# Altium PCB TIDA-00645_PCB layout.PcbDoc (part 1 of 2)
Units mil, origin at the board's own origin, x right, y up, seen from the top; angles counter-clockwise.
Board outline 3000 x 2000 mil, 2 copper layers (Top Layer, Bottom Layer), stack 62 mil thick; 97 components, 65 nets, 273 pads, 637 vias.
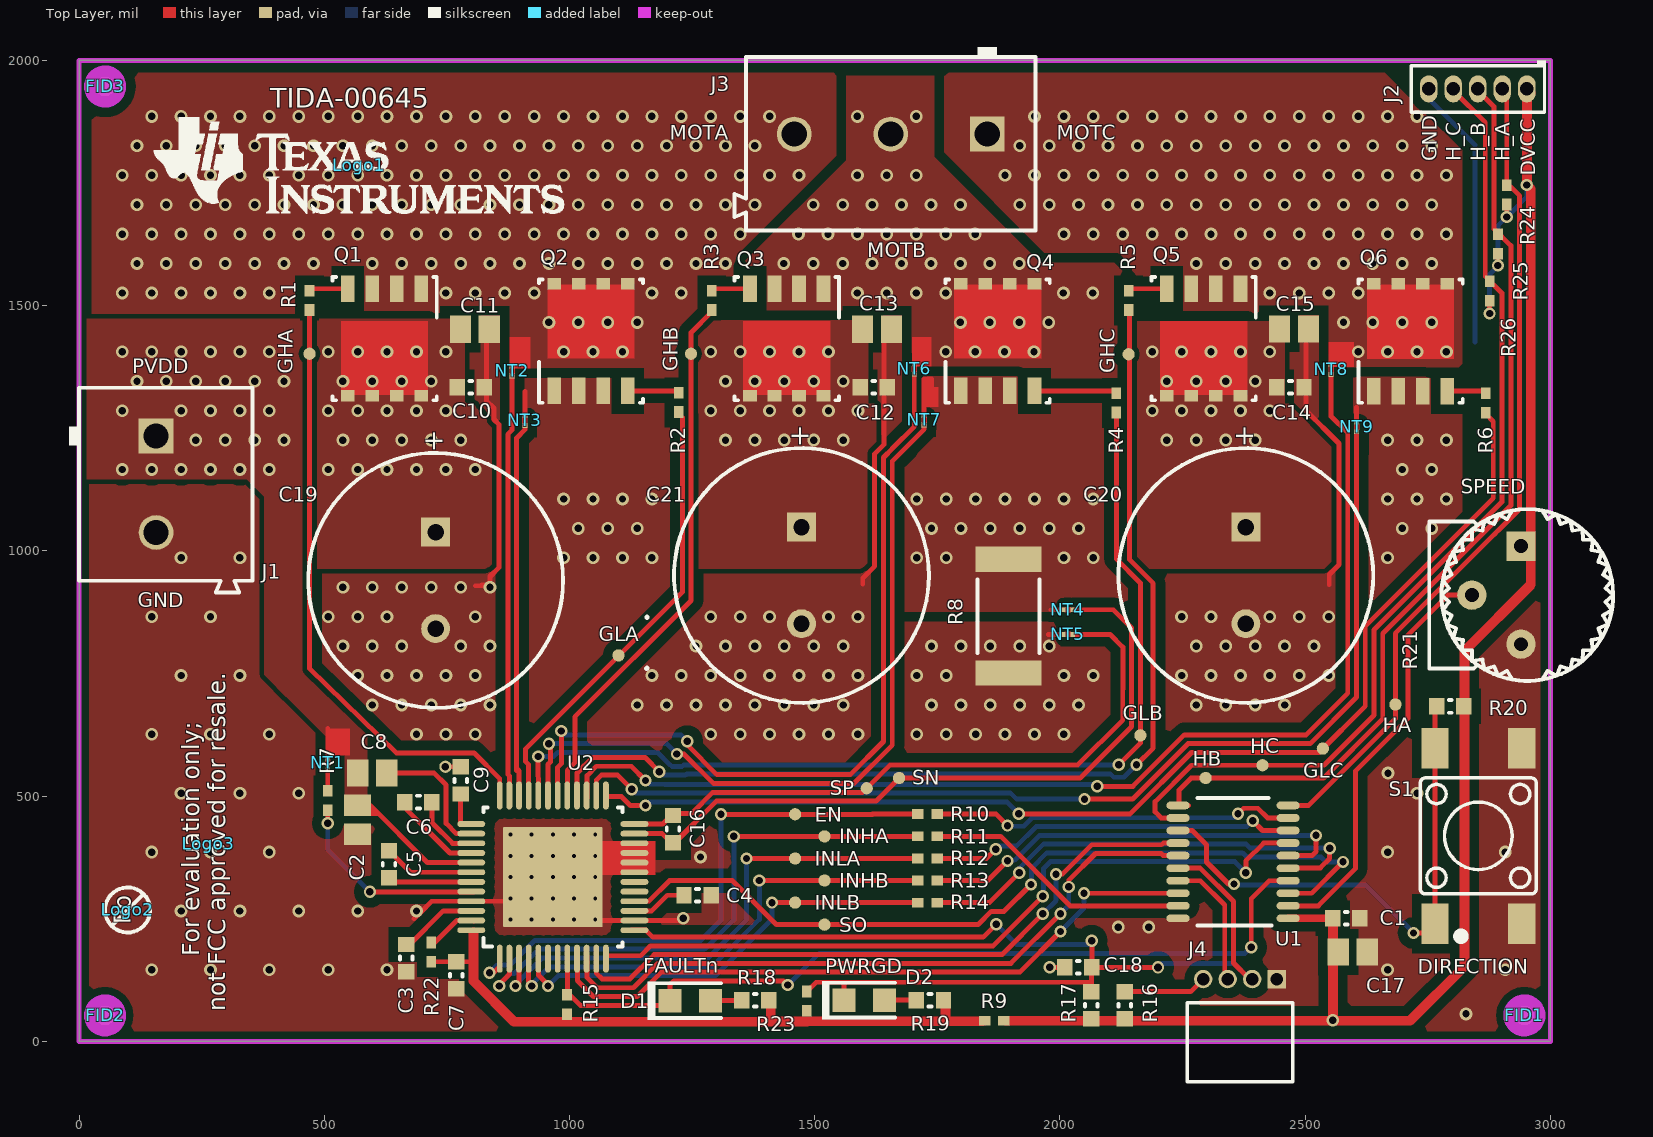
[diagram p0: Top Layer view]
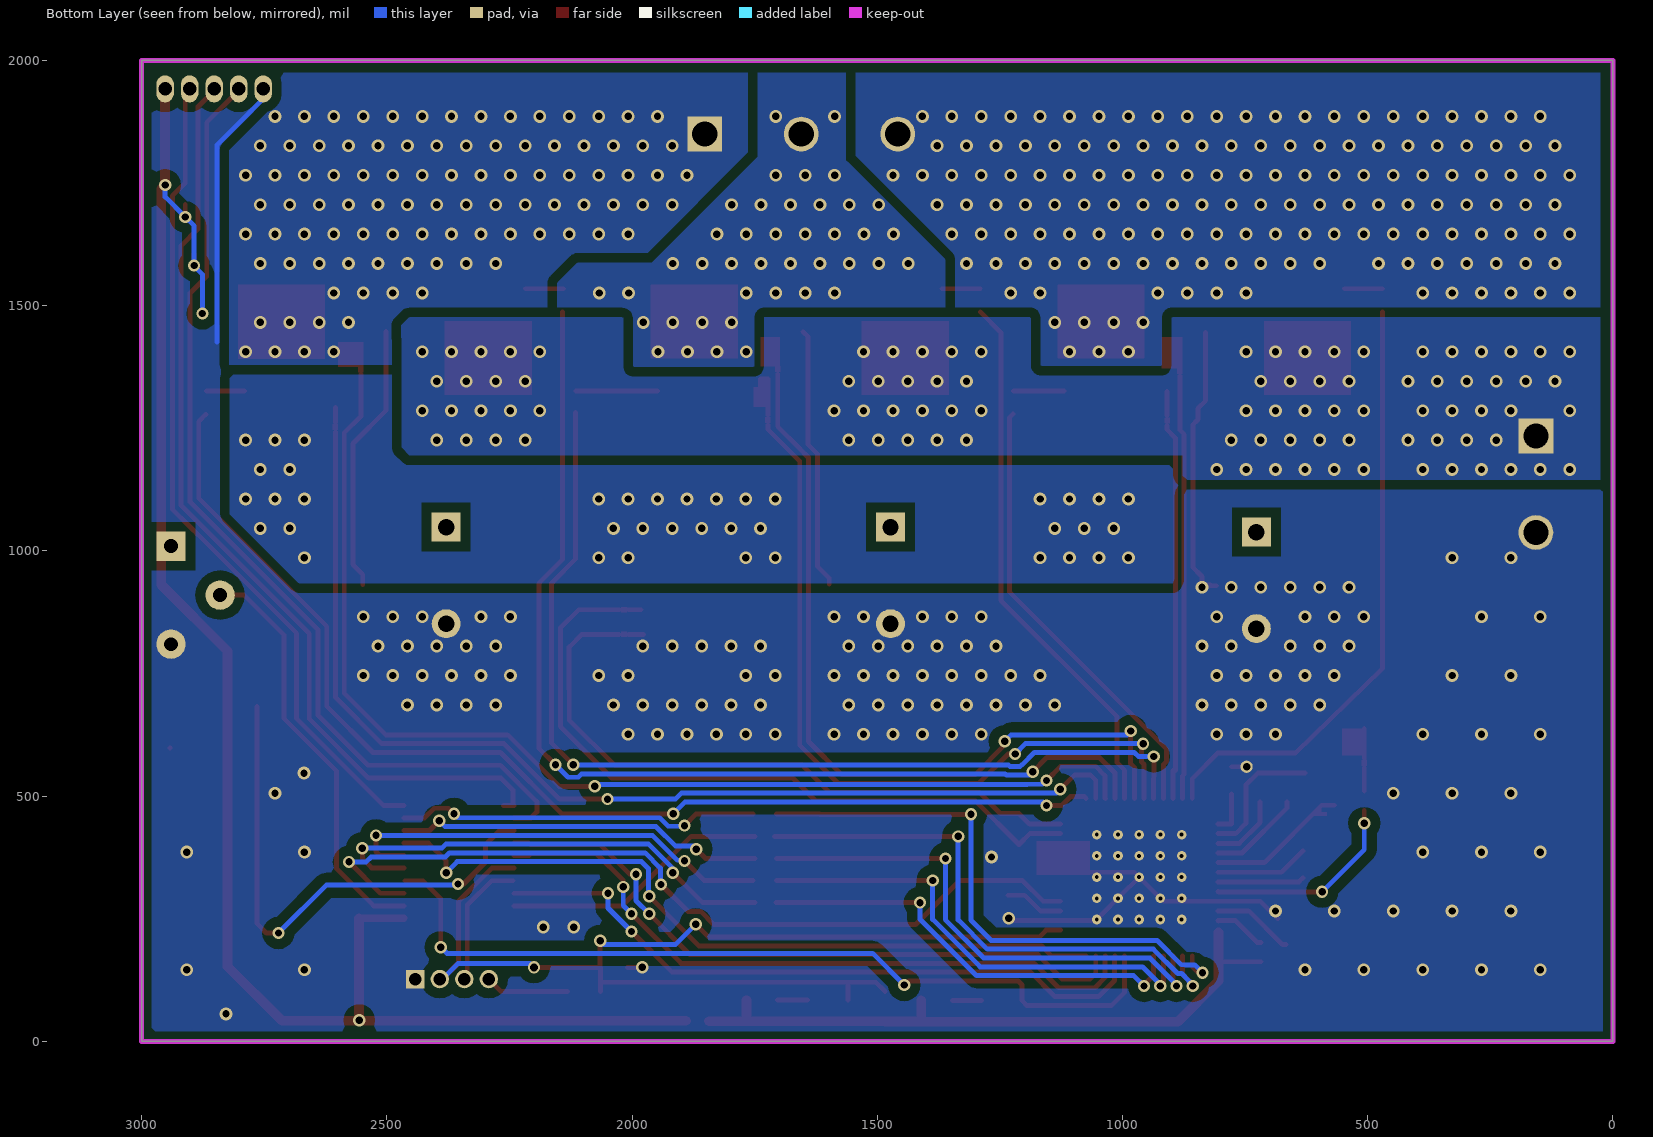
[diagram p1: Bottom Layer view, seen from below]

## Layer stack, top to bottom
Top Solder: solder mask 0.4, Solder Resist, Dk 3.5
Top Layer: signal copper 1.4
Dielectric1: core 59.2, FR-4, Dk 4.8
Bottom Layer: signal copper 1.4
Bottom Solder: solder mask 0.4, Solder Resist, Dk 3.5

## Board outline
0,0 0,2000 3000,2000 3000,0 0,0

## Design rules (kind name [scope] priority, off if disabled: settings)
AcuteAngle [All] p1: minimum=4.50000000000000E+0001 checktracksonly=FALSE
AssemblyTestPointUsage [All] p1: valid=2
Clearance Clearance_1 [InNamedPolygon('Top Layer-PVDD')] p1: gap=10
Clearance Clearance_Keepouts [((IsTrack Or IsArc) And Not InPoly) And IsFree and IsKeepOut vs ((IsTrack Or IsArc) And Not InPoly) And IsFree and IsKeepOut] p2: gap=0
Clearance Clearance_BoardEdge_MountingHoles [OnCopper and InComponentClass('Mounting Holes') vs IsKeepOut] p3: gap=40
Clearance Clearance_BoardEdge_Poly [OnCopper and InPoly vs IsKeepOut] p4: gap=15
Clearance Clearance_BoardEdge [OnCopper and Not InComponentClass('Logo') and not InComponentClass('FiducialMark') and not InRegion(1000,500,4000,800) and Not IsKeepout vs IsKeepOut] p5: gap=25
Clearance Clearance_Poly [InPolygon] p6: gap=20
Clearance [All] p7: gap=7.87
ComponentClearance ComponentClearance_MountingHoles_FiducialMarks [InComponentClass('Mounting Holes') vs InComponentClass('FiducialMark')] p1: gap=50 collisioncheckmode=3 verticalgap=10 showdistances=FALSE
ComponentClearance ComponentClearance_Shunt [InComponentClass('Header') vs InComponentClass('Shunt')] p2: gap=0 collisioncheckmode=3 verticalgap=0 showdistances=FALSE
ComponentClearance ComponentClearance_Logo [InComponentClass('Logo')] p3: gap=50 collisioncheckmode=3 verticalgap=10 showdistances=FALSE
ComponentClearance ComponentClearance_ScrewToNut [(HasFootprint('NY PMS 440 0025 PH')) vs (HasFootprint('Keystone_1902C'))] p4: gap=5 collisioncheckmode=3 verticalgap=10 showdistances=FALSE
ComponentClearance ComponentClearance_MountingHoles [InComponentClass('Mounting Holes')] p5: gap=250 collisioncheckmode=3 verticalgap=100000 showdistances=FALSE
ComponentClearance ComponentClearance_SmallPassives [HasFootprint('0201*') or HasFootprint('0402*') or HasFootprint('0508') or HasFootprint('0603*') or HasFootprint('0612') or HasFootprint('0805*') or HasFootprint('0815*') or HasFootprint('0830*') or HasFootprint('1206*') or HasFootprint('1210*') or HasFootprint('1808*') or HasFootprint('1812*') or HasFootprint('1825*') or HasFootprint('2010*') or HasFootprint('2220*') or HasFootprint('2225*') or HasFootprint('2512*') or HasFootprint('2728*') or HasFootprint('3518*') vs HasFootprint('0201*') or HasFootprint('0402*') or HasFootprint('0508') or HasFootprint('0603*') or HasFootprint('0612') or HasFootprint('0805*') or HasFootprint('0815*') or HasFootprint('0830*') or HasFootprint('1206*') or HasFootprint('1210*') or HasFootprint('1808*') or HasFootprint('1812*') or HasFootprint('1825*') or HasFootprint('2010*') or HasFootprint('2220*') or HasFootprint('2225*') or HasFootprint('2512*') or HasFootprint('2728*') or HasFootprint('3518*')] p6: gap=20 collisioncheckmode=3 verticalgap=10 showdistances=FALSE
ComponentClearance ComponentClearance_THtoSMT [IsThruComponent vs IsSMTComponent] p7: gap=100 collisioncheckmode=3 verticalgap=30 showdistances=FALSE
ComponentClearance ComponentClearance_THtoTH [IsThruComponent vs IsThruComponent] p8: gap=118.11 collisioncheckmode=3 verticalgap=30 showdistances=FALSE
ComponentClearance [All] p9: gap=40 collisioncheckmode=3 verticalgap=10 showdistances=FALSE
DiffPairsRouting [All] p1: maxlimit=100 minlimit=10 mostfreqgap=10 toplayer_minwidth=10 toplayer_maxwidth=15 toplayer_prefwidth=15 bottomlayer_minwidth=10 bottomlayer_maxwidth=15 bottomlayer_prefwidth=15 maxuncoupledlength=1000
FabricationTestPointUsage TestPointUsage [All] p1: valid=2 allowmultiple=FALSE
FabricationTestpoint Testpoint [All] p1: side=3 testpointundercomponent=TRUE minsize=40 maxsize=100 preferedsize=60 minholesize=0 maxholesize=40 preferedholesize=32 testpointgrid=1 allowsidetop=TRUE allowsidebottom=TRUE usegrid=TRUE gridtolerance=0.01
FanoutControl Fanout_LCC [IsLCC] p1: bgadir=Out bgaviamode=Centered fanoutstyle=Auto fanoutdirection=Alternating viagrid=1 // Fanout_LCC (Default Rule)
FanoutControl Fanout_BGA [IsBGA] p2: bgadir=Out bgaviamode=Centered fanoutstyle=Auto fanoutdirection=Alternating viagrid=1 // Fanout_BGA (Default Rule)
FanoutControl Fanout_Default [All] p4: bgadir=Out bgaviamode=Centered fanoutstyle=Auto fanoutdirection=Alternating viagrid=1 // Fanout_Default (Default Rule)
FanoutControl Fanout_Small [(CompPinCount < 5)] p5: bgadir=Out bgaviamode=Centered fanoutstyle=Auto fanoutdirection=OutThenIn viagrid=1 // Fanout_Small (Default Rule)
HoleSize [All] p1: absolutevalues=TRUE maxlimit=251 minlimit=7.8 maxpercent=80.000 minpercent=20.000
MinimumAnnularRing MinimumAnnularRing_ThermalPadVias [IsVia and InAnyComponent] p1: minimumring=5.91
MinimumAnnularRing [All] p2: minimumring=3.9
MinimumSolderMaskSliver MinimumSolderMaskSliver_Logo [InComponentClass('Logo') vs InComponentClass('Logo')] p1: minsoldermaskwidth=0.7
MinimumSolderMaskSliver [All] p2: minsoldermaskwidth=3.94
PlaneConnect [All] p1: planeconnectstyle=Direct reliefexpansion=10 reliefentries=4 reliefconductorwidth=10 reliefairgap=10
PolygonConnect [All] p1: connectstyle=Direct reliefconductorwidth=10 reliefentries=4 polygonreliefangle="90 Angle" airgapwidth=10
RoutingVias ThermalPadVias [IsVia and InAnyComponent] p1: holewidth=7.87 width=19.68 viastyle="Through Hole" minholewidth=7.87 minwidth=19.68 maxholewidth=12.99 maxwidth=23.62
RoutingVias [All] p2: holewidth=16 width=34 viastyle="Through Hole" minholewidth=7.8 minwidth=25 maxholewidth=40 maxwidth=65
SilkToBoardRegionClearance [Not ((IsComment or IsDesignator) And (Hide <> 'False')) and not InRegion(1000,500,4000,800)] p1:
SilkToSilkClearance SilkToSilkClearance_Pb-FreeLogo [(HasFootprint('Pb-Free_Overlay_Medium') OR HasFootprint('Pb-Free_Overlay_Small')) vs (HasFootprint('Pb-Free_Overlay_Medium') OR HasFootprint('Pb-Free_Overlay_Small'))] p1: silktosilkclearance=0
SilkToSilkClearance [All] p2: silktosilkclearance=5
SilkToSolderMaskClearance "Silk to Solder Mask Opening" [All] p1: minsilkscreentomaskgap=1 clearancetoexposedcopper=FALSE
SolderMaskExpansion [All] p1: expansion=1.97
UnpouredPolygon [All] p1: allowunpoured=FALSE
Width [All] p1: maxlimit=100 minlimit=6 preferedwidth=10 checkconnectedcopper=TRUE
14 further rules are at their usual default settings.

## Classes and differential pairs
component class TIDA-00645_Hardware: !PCB FID1 FID2 FID3 Logo1 Logo2 Logo3 ZZ2 ZZ3 ZZ4
component class Logo: Logo1
component class FiducialMark: FID1 FID2 FID3
component class AssemblyNote: ZZ2 ZZ3 ZZ4
component class TIDA-00645_Schematic: C1 C2 C3 C4 C5 C6 C7 C8 C9 C10 C11 C12 C13 C14 C15 C16 C17 C18 C19 C20 C21 D1 D2 EN GHA GHB GHC GLA GLB GLC HA HB HC INHA INHB INLA INLB J1 J2 J3 J4 NT1 NT2 NT3 NT4 NT5 NT6 NT7 NT8 NT9 Q1 Q2 Q3 Q4 Q5 Q6 R1 R2 R3 R4 R5 R6 R7 R8 R9 R10 R11 R12 R13 R14 R15 R16 R17 R18 R19 R20 R21 R22 R23 R24 R25 R26 S1 SN SO SP U1 U2
component class Header: J2
differential pair S: +S_P -S_N

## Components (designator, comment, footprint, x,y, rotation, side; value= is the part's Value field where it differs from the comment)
C1 "C0603C104K8RACTU" 0603L 2584,251 r0 top
C2 "C2012X5R1H475K125AB" 0805L 568,452 r270 top
C3 "GRM185R61A105KE36D" 0603L 667,170 r270 top
C4 "GRM185R61A105KE36D" 0603L 1261,298 r0 top
C5 "GRM188R71H473KA61D" 0603L 632,361 r270 top
C6 "GRM188R71H473KA61D" 0603L 692,488 r0 top
C7 "GRM185R61A105KE36D" 0603L 769,135 r270 top
C8 "C2012X5R1H225K125AB" 0805L 598,547 r0 top
C9 "GRM185R61A105KE36D" 0603L 778,532 r270 top
C10 "GCM188R71H104KA57D" 0603L 799,1334 r0 top
C11 "GRM21BR71H105KA12L" 0805L 807,1452 r0 top
C12 "GCM188R71H104KA57D" 0603L 1620,1334 r0 top
C13 "GRM21BR71H105KA12L" 0805L 1627,1452 r0 top
C14 "GCM188R71H104KA57D" 0603L 2470,1334 r0 top
C15 "GRM21BR71H105KA12L" 0805L 2477,1453 r0 top
C16 "GRM188R71C102KA01D" 0603L 1211,433 r90 top
C17 "C2012X7R1A475M" 0805L 2597,182 r0 top
C18 "GRM188R71C102KA01D" 0603L 2037,151 r180 top
C19 "63ZLH470M12.5X25" ZLH_1250x2500 727,940 r270 top
C20 "63ZLH470M12.5X25" ZLH_1250x2500 2379,950 r270 top
C21 "63ZLH470M12.5X25" ZLH_1250x2500 1473,950 r270 top
D1 "nFAULT" LED_LTST-C170 1246,83 r180 top
D2 "PWRGD" LED_LTST-C170 1601,84 r180 top
EN "TESTPOINT" TP_25MIL-SMT 1460,463 r90 top
FID1 "Fiducial" Fiducial10-20 2947,53 r0 top
FID2 "Fiducial" Fiducial10-20 53,53 r0 top
FID3 "Fiducial" Fiducial10-20 53,1947 r0 top
GHA "TESTPOINT" TP_25MIL-SMT 470,1402 r90 top
GHB "TESTPOINT" TP_25MIL-SMT 1247.68,1402 r90 top
GHC "TESTPOINT" TP_25MIL-SMT 2140,1401 r90 top
GLA "TESTPOINT" TP_25MIL-SMT 1100,787 r90 top
GLB "TESTPOINT" TP_25MIL-SMT 2164,624 r90 top
GLC "TESTPOINT" TP_25MIL-SMT 2536,597 r90 top
HA "TESTPOINT" TP_25MIL-SMT 2684,687 r90 top
HB "TESTPOINT" TP_25MIL-SMT 2297,537 r90 top
HC "TESTPOINT" TP_25MIL-SMT 2413,563 r90 top
INHA "TESTPOINT" TP_25MIL-SMT 1520,418 r90 top
INHB "TESTPOINT" TP_25MIL-SMT 1520,328 r90 top
INLA "TESTPOINT" TP_25MIL-SMT 1460,373 r90 top
INLB "TESTPOINT" TP_25MIL-SMT 1460,283 r90 top
J1 "691 101 710 002" Wurth_691101710002 157,1136 r270 top
J2 "GRPB051VWVN-RC" Sullins_GRPB051VWVN-RC 2852,1942 r180 top
J3 "691 101 710 003" Wurth_691101710003 1655,1850 r180 top
J4 "851-43-004-20-001000" CONN_851-43-004-20-001000 2367,127 r0 top
Logo1 "Texas Instruments" TI_Stacked_Overlay_Small 571,1786 r0 top
Logo2 "Pb-Free Symbol" Pb-Free_Overlay_Small 99,268 r90 top
Logo3 "FCC disclaimer" FCC_disclaimer_stacked 264,403 r90 top
NT1 "Net-Tie" Net-Tie_10mil 507,568 r90 top net-tie
NT2 "Net-Tie" Net-Tie_10mil 883,1367 r90 top net-tie
NT3 "Net-Tie" Net-Tie_10mil 909,1266 r90 top net-tie
NT4 "Net-Tie" Net-Tie_10mil 2016,880 r180 top net-tie
NT5 "Net-Tie" Net-Tie_10mil 2016,830 r180 top net-tie
NT6 "Net-Tie" Net-Tie_10mil 1703,1371 r90 top net-tie
NT7 "Net-Tie" Net-Tie_10mil 1723,1267 r90 top net-tie
NT8 "Net-Tie" Net-Tie_10mil 2553,1370 r90 top net-tie
NT9 "Net-Tie" Net-Tie_10mil 2605,1253 r90 top net-tie
Q1 "CSD18533Q5A" TRANS_NexFET_Q5B 622.91,1425.48 r270 top
Q2 "CSD18533Q5A" TRANS_NexFET_Q5B 1043.91,1435.48 r90 top
Q3 "CSD18533Q5A" TRANS_NexFET_Q5B 1442.91,1425.48 r270 top
Q4 "CSD18533Q5A" TRANS_NexFET_Q5B 1872.91,1435.48 r90 top
Q5 "CSD18533Q5A" TRANS_NexFET_Q5B 2292.91,1425.48 r270 top
Q6 "CSD18533Q5A" TRANS_NexFET_Q5B 2714.91,1435.3 r90 top
R1 "RC0402JR-070RL" 0402L 470,1511 r90 top
R2 "RC0402JR-070RL" 0402L 1223,1303 r90 top
R3 "RC0402JR-070RL" 0402L 1290,1511 r90 top
R4 "RC0402JR-070RL" 0402L 2115,1302 r90 top
R5 "RC0402JR-070RL" 0402L 2140,1511 r90 top
R6 "RC0402JR-070RL" 0402L 2868,1301.83 r90 top
R7 "CRCW0402100RJNED" 0402L 507,491 r90 top
R8 "PMR100HZPFU10L0" 2512 1895,867 r90 top
R9 "RC0402JR-070RL" 0402L 1866,42 r180 top
R10 "RC0402JR-070RL" 0402L 1730,463.79 r180 top
R11 "RC0402JR-070RL" 0402L 1730,418 r180 top
R12 "RC0402JR-070RL" 0402L 1730,373 r180 top
R13 "RC0402JR-070RL" 0402L 1730,328 r180 top
R14 "RC0402JR-070RL" 0402L 1730,283 r180 top
R15 "CRCW040210K0JNED" 0402L 995,75 r270 top
R16 "CRCW06030000Z0EA" 0603L 2132,74 r270 top
R17 "CRCW060347K0JNEA" 0603L 2064,74 r270 top
R18 "RC0603FR-07330RL" 0603L 1379,84 r0 top
R19 "CRCW06031K50JNEA" 0603L 1735,84 r0 top
R20 "CRCW060347K0JNEA" 0603L 2796,683 r0 top
R21 "3352P-1-204LF" Bourns_3352P 2940,910 r0 top
R22 "RC0402JR-070RL" 0402L 718,182 r270 top
R23 "CRCW040210K0JNED" 0402L 1484,82 r270 top
R24 "CRCW04022K00JNED" 0402L 2911,1726 r270 top
R25 "CRCW04022K00JNED" 0402L 2893,1626 r270 top
R26 "CRCW04022K00JNED" 0402L 2876,1530 r270 top
S1 "4-1437565-1" SW_FSM4JSMA 2853,419 r180 top
SN "TESTPOINT" TP_25MIL-SMT 1672,537 r90 top
SO "TESTPOINT" TP_25MIL-SMT 1520,238 r90 top
SP "TESTPOINT" TP_25MIL-SMT 1606,516 r90 top
U1 "MSP430G2553IPW20" PW0020A_L 2353,366 r180 top
U2 "DRV83053EPHPRQ1" PHP0048G_N 966,335 r90 top
ZZ2 "These assemblies are ESD sensitive, ESD precautions shall be observed." AssemblyNote 4148,972 r90 top
ZZ3 "These assemblies must be clean and free from flux and all contaminants. Use of no clean flux is not acceptable." AssemblyNote 3971,972 r90 top
ZZ4 "These assemblies must comply with workmanship standards IPC-A-610 Class 2, unless otherwise specified." AssemblyNote 3793,972 r90 top

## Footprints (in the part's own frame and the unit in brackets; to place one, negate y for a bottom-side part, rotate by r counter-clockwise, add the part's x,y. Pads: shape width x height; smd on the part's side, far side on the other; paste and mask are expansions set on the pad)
0402L [mm] "0402 from SM-752 data"
  rect 0.6x0.5 smd: 1(-0.5,0) 2(0.5,0)
  body extent -0.55,-0.3 0.55,0.3, height 0.6
0603L [mm] "0603 from SM-752 data"
  rect 0.8x0.85 smd: 1(-0.7,0) 2(0.7,0)
  silkscreen extent -0.07,-0.33 0.07,0.33, body extent -0.87,-0.47 0.87,0.47, height 0.85
0805L [mm] "0805 from SM-752 data"
  rect 1.1x1.4 smd: 1(-0.75,0) 2(0.75,0)
  body extent -1.1,-0.72 1.1,0.72, height 1.45
2512 [mm] "Chip Resistor, Body 6.3x3.2mm, IPC Medium Density"
  rect 1.3x3.4 smd: 1(-2.95,0) 2(2.95,0)
  silkscreen extent -1.9,-1.6 1.9,1.6, body extent -3.22,-1.67 3.22,1.67, height 0.71
AssemblyNote [mil] "Assembly Note"
Bourns_3352P [mil] "Bourns"
  rect 60x60 hole 28: 1(0,100)
  round 60 hole 28: 2(-100,0) 3(0,-100)
  silkscreen extent -187,-175 188,175, body extent -187,-175 193,175, height 212
CONN_851-43-004-20-001000 [mm] "MILL-MAX"
  rect 0.95x0.95 hole 0.65: 1(1.905,0)
  round 0.95 hole 0.65: 2(0.635,0) 3(-0.635,0) 4(-1.905,0)
  silkscreen extent -2.73,-5.31 2.73,-1.22, body extent -2.73,-5.31 2.73,0.23, height 2.23
FCC_disclaimer_stacked [mil]
Fiducial10-20 [mm]
  round 1 smd mask+0.5: 1(0,0)
  Top Layer keep-out circle w1.178: c0,0 r0.5
LED_LTST-C170 [mm] "LITE-ON"
  rect 1.2x1.2 smd: 1(-1.05,0) 2(1.05,0)
  silkscreen extent -1.6,-1 2.2,1, body extent -1.05,-0.67 1.05,0.67, height 1.1
Net-Tie_10mil [mil] "10mil net tie, no solder mask opening, no solder paste"
  rect 10x10 smd paste-5 mask-5: 1(-10,0) 2(10,0)
  Top Layer region: -6,5 6,5 6,-5 -6,-5
Pb-Free_Overlay_Small [mil]
  silkscreen extent -46,-46 46,46
PHP0048G_N [mm] "QFP, 48-Leads, Body 7x7mm, Pitch 0.5mm, Thermal Pad 5.17X5.17mm, IPC Medium Density"
  oval 1.45x0.3 smd: 1(-4.225,2.75) 2(-4.225,2.25) 3(-4.225,1.75) 4(-4.225,1.25) 5(-4.225,0.75) 6(-4.225,0.25) 7(-4.225,-0.25) 8(-4.225,-0.75) 9(-4.225,-1.25) 10(-4.225,-1.75) 11(-4.225,-2.25) 12(-4.225,-2.75) 25(4.225,-2.75) 26(4.225,-2.25) 27(4.225,-1.75) 28(4.225,-1.25) 29(4.225,-0.75) 30(4.225,-0.25) 31(4.225,0.25) 32(4.225,0.75) 33(4.225,1.25) 34(4.225,1.75) 35(4.225,2.25) 36(4.225,2.75)
  oval 0.3x1.45 smd: 13(-2.75,-4.225) 14(-2.25,-4.225) 15(-1.75,-4.225) 16(-1.25,-4.225) 17(-0.75,-4.225) 18(-0.25,-4.225) 19(0.25,-4.225) 20(0.75,-4.225) 21(1.25,-4.225) 22(1.75,-4.225) 23(2.25,-4.225) 24(2.75,-4.225) 37(2.75,4.225) 38(2.25,4.225) 39(1.75,4.225) 40(1.25,4.225) 41(0.75,4.225) 42(0.25,4.225) 43(-0.25,4.225) 44(-0.75,4.225) 45(-1.25,4.225) 46(-1.75,4.225) 47(-2.25,4.225) 48(-2.75,4.225)
  rrect2% 5.17x5.17 smd: 49(0,0)
  silkscreen extent -3.6,-3.6 3.6,3.6, body extent -4.51,-4.51 4.51,4.51, height 1.2
PW0020A_L [mm] "TSOP, 20-Leads, Body 6.5x4.4mm, Pitch 0.65mm, IPC High Density"
  oval 1.2x0.4 smd: 1(-2.85,2.925) 2(-2.85,2.275) 3(-2.85,1.625) 4(-2.85,0.975) 5(-2.85,0.325) 6(-2.85,-0.325) 7(-2.85,-0.975) 8(-2.85,-1.625) 9(-2.85,-2.275) 10(-2.85,-2.925) 11(2.85,-2.925) 12(2.85,-2.275) 13(2.85,-1.625) 14(2.85,-0.975) 15(2.85,-0.325) 16(2.85,0.325) 17(2.85,0.975) 18(2.85,1.625) 19(2.85,2.275) 20(2.85,2.925)
  silkscreen extent -2,-3.3 1.85,3.3, body extent -3.21,-3.25 3.21,3.25, height 1
Sullins_GRPB051VWVN-RC [mm] "SULLINS"
  oval 0.9x1.4 hole 0.7: 1(-2.54,0) 2(-1.27,0) 3(0,0) 4(1.27,0) 5(2.54,0)
  silkscreen extent -3.52,-1.47 3.45,1.2, body extent -3.42,-1.17 3.42,1.17, height 4.2
SW_FSM4JSMA [mm] "Alcoswitch"
  rect 1.4x2.1 smd: 1(2.25,4.55) 2(2.25,-4.55) 3(-2.25,4.55) 4(-2.25,-4.55)
  silkscreen extent -3,-3 3,5.4, body extent -3,-5 3,5, height 5.1
TI_Stacked_Overlay_Small [mil]
  silkscreen extent -418,-98 418,98
TP_25MIL-SMT [mil]
  round 25 smd mask-2.5: 1(0,0)
TRANS_NexFET_Q5B [mm] "TI recommended land pattern (nominal) November 2012"
  rect 1.372x0.71 smd paste-0.4: 1(-2.776,1.905) 2(-2.776,0.635) 3(-2.776,-0.635) 4(-2.776,-1.905)
  rect 0.59x0.71 smd paste-0.3: 5(2.776,-1.905) 6(2.776,-0.635) 7(2.776,0.635) 8(2.776,1.905)
  Top Layer region: -1.106,-2.26 2.744,-2.26 2.744,2.26 -1.106,2.26
  silkscreen extent -3.38,-2.7 3,2.7, body extent -3.23,-2.55 2.87,2.55, height 1.06
Wurth_691101710002 [mm] "Terminal Block, 5 mm, 2x1, TH"
  rect 1.8x1.8 hole 1.3: 1(-2.5,0)
  round 1.8 hole 1.3: 2(2.5,0)
  silkscreen extent -5,-4.5 5.6,5, body extent -5.6,-4 5.6,5, height 12.5
Wurth_691101710003 [mm] "Terminal Block, 5 mm, 3x1, TH"
  rect 1.8x1.8 hole 1.3: 1(-5,0)
  round 1.8 hole 1.3: 2(0,0) 3(5,0)
  silkscreen extent -7.5,-4.5 8.1,5, body extent -8.1,-4 8.1,5, height 12.5
ZLH_1250x2500 [mm] "Rubycon"
  rect 1.5x1.5 hole 0.85: 1(-2.5,0)
  round 1.5 hole 0.85: 2(2.5,0)
  silkscreen extent -6.6,-6.6 6.6,6.6, body extent -6.45,-6.49 6.49,6.49, height 26.51

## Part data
C1: "CAP, CERM, 0.1uF, 10V, +/-10%, X7R, 0603"
C2: "CAP, CERM, 4.7 µF, 50 V, +/- 10%, X5R, 0805"
C3 C4 C7 C9: "CAP, CERM, 1 ?F, 10 V, +/- 10%, X5R, 0603"
C5 C6: "CAP, CERM, 0.047 µF, 50 V, +/- 10%, X7R, 0603"
C8: "CAP, CERM, 2.2 µF, 50 V, +/- 10%, X5R, 0805"
C10 C12 C14: "CAP, CERM, 0.1 µF, 50 V, +/- 10%, X7R, 0603"
C11 C13 C15: "CAP, CERM, 1uF, 50V, +/-10%, X7R, 0805"
C16 C18: "CAP, CERM, 1000pF, 16V, +/-10%, X7R, 0603"
C17: "CAP, CERM, 4.7uF, 10V, +/-20%, X7R, 0805"
C19 C20 C21: "CAP, AL, 470 µF, 63 V, +/- 20%, 0.043 ohm, TH"
D1 D2: library part LTST-C170KRKT, "LED, Red, SMD"
EN GHA GHB GHC GLA GLB GLC HA HB HC INHA INHB INLA INLB SN SO SP: "TEST POINT.  No entry in BOM."
FID1 FID2 FID3: "Fiducial mark.  There is nothing to buy or mount."
J1: "Terminal Block, 5 mm, 2x1, Tin, TH"
J2: "Header, 50mil, 5x1, Gold, TH"
J3: "Terminal Block, 5 mm, 3x1, Tin, TH"
J4: "SOCKET .050\" GRID SIP 4 POS R/A, TH"
Logo1: library part TI_Logo, "Texas Instrument Corporate Signature"
Logo2: library part Pb-Free
Logo3: library part FCC_disclaimer, "FCC_disclaimer"
NT1 NT2 NT3 NT4 NT5 NT6 NT7 NT8 NT9: "Single point connection between nets."
Q1 Q2 Q3 Q4 Q5 Q6: library part CSD18540Q5B, "MOSFET, N-CH, 60 V, 28 A, SON 5x6mm"
R1 R2 R3 R4 R5 R6 R9 R10 R11 R12 R13 R14 R22: "RES, 0, 5%, 0.063 W, 0402"
R7: "RES, 100, 5%, 0.063 W, 0402"
R8: "RES, 0.01, 1%, 2 W, 2512"
R15 R23: "RES, 10 k, 5%, 0.063 W, 0402"
R16: "RES, 0 ohm, 5%, 0.1W, 0603"
R17: "RES, 47k ohm, 5%, 0.1W, 0603"
R18: "RES, 330, 1%, 0.1 W, 0603"
R19: "RES, 1.5 k, 5%, 0.1 W, 0603"
R20: "RES 47K OHM 1/10W 5% 0603 SMD"
R21: "Trimmer, 200 K, 0.5 W, TH"
R24 R25 R26: "RES, 2.0 k, 5%, 0.063 W, 0402"
S1: "SWITCH TACTILE SPST-NO 0.05A 12V"
U1: "16 MHz Mixed Signal Microcontroller with 16 KB Flash, 512 B SRAM and 24 GPIOs, -40 to 85 degC, 20-pin SOP (PW), Green (RoHS & no Sb/Br)"
U2: "Three Phase Automotive Gate Driver with Three Integrated Current Shunt Amplifiers and Voltage Regulator, PHP0048G"
ZZ2 ZZ3 ZZ4: library part AssemblyNote

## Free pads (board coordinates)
  round 25 hole 15: 0(747,560)

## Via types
v1: diameter 26, hole 15, Top Layer to Bottom Layer, tented both sides, 555 vias
v2: diameter 25, hole 15, Top Layer to Bottom Layer, 56 vias
v3: diameter 19.68, hole 7.87, Top Layer to Bottom Layer, 25 vias
v4: diameter 25, hole 16, Top Layer to Bottom Layer, 1 vias

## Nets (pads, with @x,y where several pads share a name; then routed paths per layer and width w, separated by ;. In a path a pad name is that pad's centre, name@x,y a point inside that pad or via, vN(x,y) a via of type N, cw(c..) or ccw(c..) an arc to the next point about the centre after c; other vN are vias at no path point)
BRIDGE: NT3.2 NT4.2 NT7.2 NT9.2 Q2.1 Q2.2 Q2.3 Q4.1 Q4.2 Q4.3 Q6.1 Q6.2 Q6.3 R8.2 | length 192.1
  Top Layer w10: NT3.2@909,1276 909,1325.08 ; NT7.2@1723,1277 1723,1351 1738,1351 ; 1982,880 NT4.2@2006,880 ; NT9.2@2605,1263 2605,1293
  other v1: 988,986 1048,986 1108,986 1168,986 1708,986 1768,986 2008,986 2068,986 2668,986 1018,1046 1078,1046 1138,1046 1738,1046 1798,1046 1858,1046 1918,1046 1978,1046 2038,1046 2698,1046 2758,1046 988,1106 1048,1106 1108,1106 1168,1106 1708,1106 1768,1106 1828,1106 1888,1106 1948,1106 2008,1106 2068,1106 2668,1106 2728,1106 2788,1106 2698,1166 2758,1166 2668,1226 2728,1226 2788,1226
DVCC: C1.1 C17.1 J2.1 R9.1 R16.2 R17.2 R20.2 R21.1 R24.2 R25.2 R26.2 U1.1 | length 3510
  Top Layer w10: C1.1@2556.05,250.84 2556.44,250.45 C1.1@2556.44,251 C1.1@2556.2,251 ; v2(2876,1484) R26.2@2876,1510.31 ; v2(2893,1582) R25.2@2893,1606.31 ; v2(2911,1681) R24.2@2911,1706.31
  Top Layer w15: U1.1@2465.2,250.84 C1.1@2556.05,250.84
  Top Layer w20: R9.1@1890,42 2714,42 2825,153 2825,796 2960,931 2960,1010 2960,1709 2960,1738 v2(2952,1746) J2.1@2952,1942 J2.1@2960,1934 ; v2@2556.44,42.56 C1.1@2556.47,250.42
  Bottom Layer w10: v2(2876,1484) 2876,1564 2893,1581 v2(2893,1582) 2893,1663 v2(2911,1681) 2952,1722 v2(2952,1746)
  other v2: 2556,43
EN_GATE: EN.1 R10.2 U2.1 | length 1176.7
  Top Layer w10: v2(837,140) 845,140 857.73,152.73 U2.1@857.73,174.57 ; v2(1309,463) EN.1@1460,463 1617.56,463 ; 1618,463.44 R10.2@1706.03,463.44
  Bottom Layer w10: v2(837,140) 853,156 871.84,156 872.09,156.25 879.81,156.25 929.56,206 1268,206 1309,247 v2(1309,463)
EN_GATE_MSP: R10.1 U1.9 | length 745.4
  Top Layer w10: R10.1@1753.62,463.79 1869.21,463.79 v2(1893,440) ; v2(2363,464) 2374.37,475.37 2403.51,475.37 2423.32,455.57 2463.24,455.57 U1.9@2465.2,455.57
  Bottom Layer w10: v2(1893,440) 1894.37,438.63 1926.51,438.63 1943.88,456 2355,456 v2(2363,464)
FAULT: D1.2 R15.1 U1.4 U2.8 | length 1742.4
  Top Layer w10: U2.8@995.53,174.57 995.53,100.06 1022.59,73 1194.66,73 D1.2@1204.66,83 1204.66,114.92 1213,123.26 1436.74,123.26 v2(1445,115) ; v2(2390,192) 2390,291 2426.61,327.61 U1.4@2463.24,327.61
  Bottom Layer w10: v2(1445,115) 1509.37,179.37 2377.37,179.37 v2(2390,192)
GH_A: GHA.1 R1.1 U2.36 | length 1246.9
  Top Layer w10: R1.1@470,1487.38 470,760 646.75,588.25 805.19,588.25 857.73,535.71 U2.36@857.73,495.43
GH_B: GHB.1 R3.1 U2.29 | length 1114.1
  Top Layer w10: 995.51,552.83 1011,568.32 1011,662 1247.87,898.87 1247.87,1279.78 1247.68,1279.97 1247.68,1445.06 R3.1@1290,1487.38 ; U2.29@995.53,495.43 995.53,552.81
GH_C: GHC.1 R5.1 U2.28 | length 2191.9
  Top Layer w10: U2.28@1015.21,495.43 1015.21,547.21 1047.19,578.81 1154.19,578.81 v2(1183,550) ; R5.1@2142,1487.1 2142,982 2190,934 2190,598 v2(2156,564)
  Bottom Layer w10: v2(1183,550) 1190.25,542.75 1236.91,542.75 1239.54,545.37 2102.74,545.37 2109.49,538.63 2130.63,538.63 v2(2156,564)
GL_A: GLA.1 R2.1 U2.33 | length 923.1
  Top Layer w10: U2.33@916.13,496.09 916.79,495.43 916.79,564.21 910,571 910,596 1230,916 1230,1272.38 R2.1@1223,1279.38
GL_B: GLB.1 R4.1 U2.32 | length 2041.9
  Top Layer w10: v2(936,581) U2.32@936.47,495.43 ; R4.1@2115,1282.32 2115,983.72 2164,934.72 GLB.1@2164,624 2164,608 v2(2120,564)
  Bottom Layer w10: v2(936,581) 967.88,581 976.01,589.13 1179.87,589.13 1205.75,563.25 1205.87,563.25 1208.49,560.63 1229.51,560.63 1232.13,563.25 v2@2119.25,563.25
GL_C: GLC.1 R6.1 U2.25 | length 2370.3
  Top Layer w10: U2.25@1074.27,495.43 1077.83,499 1106.12,499 1124.12,481 v2(1155,481) ; v2(1916,464) 2143.28,464 2268.28,589 2528.17,589 2622.5,683.34 2622.5,846.54 2883.5,1107.54 2883.5,1263.87 R6.1@2869,1278.38
  Bottom Layer w10: v2(1155,481) 1162.37,488.37 1891.63,488.37 v2(1916,464)
GND: C1.2 C2.2 C3.2 C4.2 C7.2 C9.1 C10.2 C11.2 C12.2 C13.2 C14.2 C15.2 C17.2 C18.2 C19.2 C20.2 C21.2 J1.2 J2.5 J4.1 NT5.2 pad.0 R8.1 R21.3 S1.3 S1.4 U1.20 U2.14 U2.19 U2.20 U2.21 U2.22 U2.45 U2.49 | length 3143.5
  Top Layer w10: 683,250 718.79,285.79 805.57,285.79 916.79,285.79 v3(966,335) ; pad.0@747,560 C9.1@778,560 ; 808,929 830.38,929 838,936.62 838,948 856.38,966.38 856.38,1257.62 846,1268 846,1291 830.5,1306.5 C11.2@830.5,1445.97 ; 821,931 v1@829.38,931 ; U2.22@1126.43,403.9 1126.43,384.21 1126.43,364.53 1126.43,344.84 975.84,344.84 v3(966,335) ; v1@1225.58,246.42 1126.43,246.42 1054.58,246.42 1044.74,256.26 1005.37,295.63 v3(966,335) ; 1598,932 1598,944.47 1622.25,968.73 1622.25,1197.93 1641,1216.68 1641,1436.47 C13.2@1651.5,1446.97 ; 1977,830 NT5.2@2006,830 ; v2(1979,151) C18.2@2009.44,151 ; C15.2@2501.5,1447.97 2501.5,1286.5 2568.88,1219.12 2568.88,971.88 2549,952 2549,931 ; S1.4@2941.58,598.13 S1.4@2942,598.55
  Bottom Layer w10: J2.5@2752,1942 2752,1922 2846,1828 2846,1426
  other v1: 2828,56 148,146 268,146 388,146 508,146 628,146 2668,146 2908,146 2119,233 2181,233 1232,251 208,266 328,266 448,266 568,266 688,266 1267,376 148,386 268,386 388,386 2668,386 2908,386 208,506 328,506 448,506 2728,506 2669,547 148,626 268,626 388,626 688,626 748,626 808,626 1288,626 1348,626 1408,626 1468,626 1528,626 1588,626 1708,626 1768,626 1828,626 1888,626 1948,626 2008,626 598,686 658,686 718,686 778,686 838,686 1138,686 1198,686 1258,686 1318,686 1378,686 1438,686 1498,686 1558,686 1738,686 1798,686 1858,686 1918,686 1978,686 2038,686 2278,686 2338,686 2398,686 2458,686 208,746 328,746 568,746 628,746 688,746 748,746 808,746 1168,746 1228,746 1288,746 1348,746 1408,746 1468,746 1528,746 1588,746 1708,746 1768,746 2008,746 2068,746 2248,746 2308,746 2368,746 2428,746 2488,746 2548,746 538,806 598,806 658,806 778,806 838,806 1258,806 1318,806 1378,806 1438,806 1498,806 1558,806 1738,806 1798,806 1858,806 1918,806 1978,806 2278,806 2338,806 2398,806 2458,806 2518,806 148,866 268,866 508,866 568,866 628,866 808,866 1288,866 1348,866 1408,866 1528,866 1588,866 2248,866 2308,866 2428,866 2488,866 2548,866 538,926 598,926 658,926 718,926 778,926 838,926 208,986 328,986
  other v3: 879.39,248.39 922.69,248.39 966,248.39 1009.31,248.39 1052.61,248.39 879.39,291.69 922.69,291.69 966,291.69 1009.31,291.69 1052.61,291.69 879.39,335 922.69,335 1009.31,335 1052.61,335 879.39,378.31 922.69,378.31 966,378.31 1009.31,378.31 1052.61,378.31 879.39,421.61 922.69,421.61 966,421.61 1009.31,421.61 1052.61,421.61
HALL_A: HA.1 J2.2 R24.1 U1.10 | length 1705.8
  Top Layer w10: U1.10@2465.2,481.16 2507.16,481.16 2684,658 2684,832.21 2886.62,1034.82 ; 2886.66,1034.82 2897.13,1045.29 ; 2897.13,1045.33 2904.67,1052.87 ; 2904.71,1052.87 2937.13,1085.29 2937.13,1724 2911,1750.13 2911,1924 2902,1933 J2.2@2902,1942 J2.2@2909.28,1934.72
HALL_B: HB.1 J2.3 R25.1 U1.11 | length 1948.3
  Top Layer w10: U1.11@2241,481 U1.11@2262,481 ; U1.11@2242.76,481.16 2242.76,512.37 2267.39,537 HB.1@2297,537 2537.72,537 2658.25,657.53 2658.25,831.74 2897.26,1070.75 ; J2.3@2852,1942 2852,1938.9 2885,1905.9 2885,1656.68 2919.25,1622.43 2919.25,1092.7 2897.3,1070.75
HALL_C: HC.1 J2.4 R26.1 U1.12 | length 2018.5
  Top Layer w10: U1.12@2240.8,455.57 2206.43,455.57 2194,468 2194,488.89 2268.11,563 2538.44,563 2640.38,664.93 2640.38,839.14 2901.38,1100.14 2901.38,1525.62 2867.13,1559.87 2867.13,1873.77 2802,1938.9 J2.4@2802,1942
INH_A: INHA.1 R11.2 U2.2 | length 1151.7
  Top Layer w10: v2(857,113) 857,115.88 877.42,136.3 U2.2@877.42,174.57 ; v2(1335,418) R11.2@1710.11,418
  Bottom Layer w10: v2(857,113) 857,115.88 863.24,122.13 864.63,122.13 864.63,123.51 879.49,138.37 887.21,138.37 936.96,188.13 1275.4,188.13 1335,247.72 v2(1335,418)
INH_A_MSP: R11.1 U1.19 | length 549.7
  Top Layer w10: R11.1@1749.68,418 1879,418 2020.57,276.43 U1.19@2240.8,276.43
INH_B: INHB.1 R13.2 U2.4 | length 984.5
  Top Layer w10: U2.4@916.79,174.57 916.79,122.21 923,116 v2(923,113) ; v2(1387,328) INHB.1@1520,328 1672.44,328 ; 1671.65,327.79 R13.2@1705.38,327.79
  Bottom Layer w10: v2(923,113) 923,115.88 959.12,152 1290.28,152 1387,248.72 v2(1387,328)
INH_B_MSP: R13.1 U1.6 | length 899.7
  Top Layer w10: R13.1@1753.62,328 1853,328 v2(1893,368) ; U1.6@2465.2,378.8 2513.8,378.8 2522,387 v2(2522,420)
  Bottom Layer w10: v2(1893,368) 1894.37,369.37 1907.81,369.37 1958.44,420 v2(2522,420)
INL_A: INLA.1 R12.2 U2.3 | length 1062.7
  Top Layer w10: v2(890,113) 897.1,120.1 U2.3@897.1,174.57 ; v2(1361,373) INLA.1@1460,373 1645.56,373 ; 1645.97,373 R12.2@1706,373
  Bottom Layer w10: v2(890,113) 890,115.88 944.12,170 1283,170 1361,248 v2(1361,373)
INL_A_MSP: R12.1 U1.8 | length 755.7
  Top Layer w10: R12.1@1749.68,373 1850,373 v2(1869,392) ; v2(2393,450) 2413.02,429.98 U1.8@2465.2,429.98
  Bottom Layer w10: v2(1869,392) 1875,398 1911.16,398 1951.16,438 2381,438 v2(2393,450)
INL_B: INLB.1 R14.2 U2.5 | length 909.9
  Top Layer w10: U2.5@936.47,174.57 936.47,135.41 956,115.88 v2(956,113) ; v2(1413,283) INLB.1@1460,283 R14.2@1706.17,283
  Bottom Layer w10: v2(956,113) 977.13,134.13 1297.68,134.13 1413,249.44 v2(1413,283)
INL_B_MSP: R14.1 U1.5 | length 972.8
  Top Layer w10: R14.1@1749.68,283 1856,283 v2(1917,344) ; U1.5@2465.2,353.2 2465.2,353.87 2530.87,353.87 2550,373 v2(2550,394)
  Bottom Layer w10: v2(1917,344) 1917,353.28 1965.84,402.13 2379.71,402.13 2387.84,394 v2(2550,394)
M_A: J3.3 NT2.2 Q1.1 Q1.2 Q1.3 Q2.5 Q2.6 Q2.7 Q2.8
  other v1: 988,1406 1048,1406 1108,1406 958,1466 1018,1466 1078,1466 1138,1466 88,1526 148,1526 208,1526 268,1526 328,1526 388,1526 748,1526 808,1526 868,1526 928,1526 1168,1526 1228,1526 118,1586 178,1586 238,1586 298,1586 358,1586 418,1586 478,1586 598,1586 658,1586 718,1586 778,1586 838,1586 898,1586 958,1586 1018,1586 1078,1586 1138,1586 1198,1586 1258,1586 1318,1586 88,1646 148,1646 208,1646 268,1646 328,1646 388,1646 448,1646 508,1646 568,1646 628,1646 688,1646 748,1646 808,1646 868,1646 928,1646 988,1646 1048,1646 1108,1646 1168,1646 1228,1646 1288,1646 1348,1646 118,1706 178,1706 238,1706 298,1706 358,1706 418,1706 478,1706 538,1706 598,1706 658,1706 718,1706 778,1706 838,1706 898,1706 958,1706 1018,1706 1078,1706 1138,1706 1198,1706 1258,1706 1318,1706 1378,1706 88,1766 148,1766 208,1766 268,1766 328,1766 388,1766 448,1766 508,1766 568,1766 628,1766 688,1766 748,1766 808,1766 868,1766 928,1766 988,1766 1048,1766 1108,1766 1168,1766 1228,1766 1288,1766 1348,1766 1408,1766 1468,1766 118,1826 178,1826 238,1826 298,1826 358,1826 418,1826 478,1826 538,1826 598,1826 658,1826 718,1826 778,1826 838,1826 898,1826 958,1826 1018,1826 1078,1826 1138,1826 1198,1826 1258,1826 1318,1826 1378,1826 148,1886 208,1886 268,1886 328,1886 388,1886 448,1886 508,1886 568,1886 628,1886 688,1886 748,1886 808,1886 868,1886 928,1886 988,1886 1048,1886 1108,1886 1168,1886 1228,1886 1288,1886 1348,1886 1408,1886
M_B: J3.2 NT6.2 Q3.1 Q3.2 Q3.3 Q4.5 Q4.6 Q4.7 Q4.8
  other v1: 1767,1406 1827,1406 1887,1406 1947,1406 1797,1466 1857,1466 1917,1466 1977,1466 1587,1526 1647,1526 1707,1526 1767,1526 2007,1526 2067,1526 1437,1586 1497,1586 1557,1586 1617,1586 1677,1586 1737,1586 1797,1586 1857,1586 1917,1586 1467,1646 1527,1646 1587,1646 1647,1646 1707,1646 1767,1646 1827,1646 1497,1706 1557,1706 1617,1706 1677,1706 1737,1706 1797,1706 1587,1766 1647,1766 1707,1766 1587,1886 1707,1886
